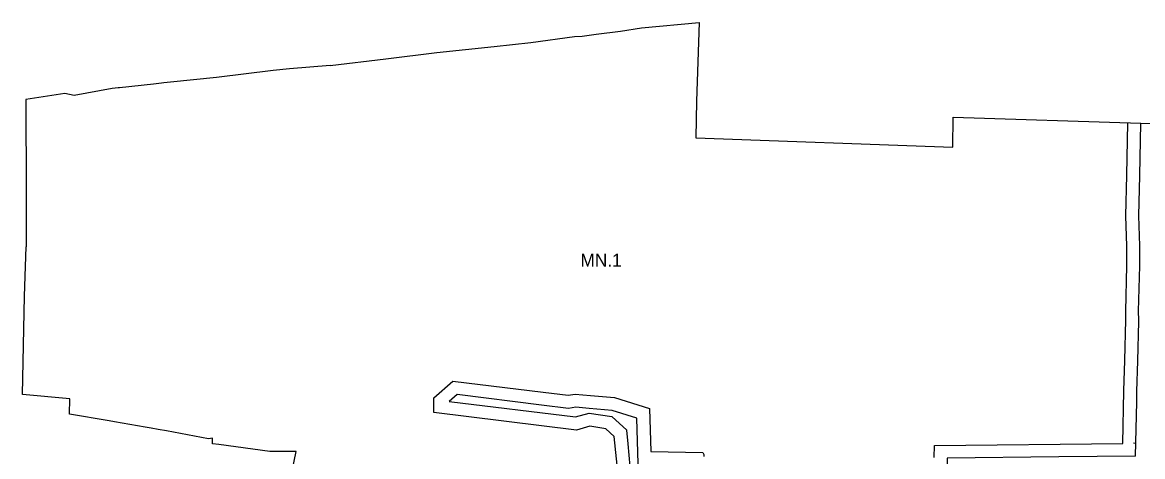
# Model space of a CAD drawing. Extents: x 7414808 to 7417449, y 5544732 to 5546764.
# Drawn here: x 7415345.7 to 7415779, y 5546060.4 to 5546228.6 of the extents above; entities that cross this region are included whole.
import ezdxf

# ---------------------------------------------------------------- set-up
doc = ezdxf.new("R2010")
doc.units = 0
for name, color, linetype in [('LIN_Linie Rozgraniczajace', 7, 'Continuous'), ('LIN_nieprzekraczale linie zabudowy', 7, 'Continuous'), ('TXT_Oznaczenia Przeznaczenia', 7, 'Continuous')]:
    doc.layers.add(name, color=color, linetype=linetype)

msp = doc.modelspace()

# ---------------------------------------------------------------- linework, layer by layer
at = {"layer": 'LIN_Linie Rozgraniczajace'}
for p, q in [((7415464.68, 5546211.88), (7415486.23, 5546214.51)), ((7415778.34, 5546189.58), (7415792.34, 5546189.15)), ((7415346.87, 5546134.03), (7415347.09, 5546141.63)), ((7415579.98, 5546065.34), (7415579.48, 5546070.64))]:
    msp.add_line(p, q, dxfattribs=at)
for points in [[(7415486.23, 5546214.51), (7415506.07, 5546216.92), (7415528.22, 5546219.22), (7415542.33, 5546220.82), (7415559.21, 5546223.15), (7415562.29, 5546223.21), (7415567.6, 5546224.08), (7415577.04, 5546225.19), (7415585.24, 5546226.49), (7415607.49, 5546228.6), (7415606.48, 5546198.05), (7415606.25, 5546183.93), (7415705.62, 5546180.27), (7415705.76, 5546191.84), (7415778.34, 5546189.58)], [(7415464.68, 5546211.88), (7415448.97, 5546210.67), (7415442.64, 5546209.99), (7415420.71, 5546207.28), (7415403.02, 5546205.41), (7415400.36, 5546205.14), (7415399.52, 5546205.05), (7415396.35, 5546204.7), (7415383.24, 5546203.24), (7415382.76, 5546203.19), (7415380.41, 5546202.93), (7415365.7, 5546200.33), (7415362.11, 5546201.04), (7415347.01, 5546198.79), (7415347.12, 5546162.5), (7415347.1, 5546147.03), (7415347.09, 5546141.63)], [(7415776.33, 5546060.55), (7415776.8, 5546081.64), (7415776.85, 5546085.7), (7415777.16, 5546097.57), (7415777.61, 5546112.72), (7415777.59, 5546113.23), (7415777.52, 5546116.75), (7415777.96, 5546134.25), (7415777.92, 5546142.06), (7415777.54, 5546153.67), (7415777.99, 5546169.34), (7415778.34, 5546189.58)], [(7415451.61, 5546062.42), (7415447.67, 5546062.39), (7415441.37, 5546062.35), (7415421.66, 5546065.13), (7415419.21, 5546065.37), (7415419.2, 5546067.57), (7415417.63, 5546067.34), (7415401.38, 5546070.4), (7415398.26, 5546070.93), (7415395.45, 5546071.43), (7415393.11, 5546071.83), (7415381.32, 5546073.87), (7415379.26, 5546074.23), (7415363.91, 5546076.89), (7415364.01, 5546082.81), (7415345.68, 5546084.46), (7415346.53, 5546122.61), (7415346.87, 5546134.03)], [(7415583.85, 5546057.58), (7415583.43, 5546075.3), (7415573.8, 5546078.32), (7415564.97, 5546079.11), (7415559.81, 5546079.62), (7415556.94, 5546079.1), (7415546.52, 5546080.39), (7415513.83, 5546084.43), (7415510.82, 5546081.8), (7415559.62, 5546075.78), (7415564.88, 5546077.31), (7415573.69, 5546075.93), (7415579.48, 5546070.64)], [(7415581.19, 5546053.19), (7415580.8, 5546056.61), (7415579.98, 5546065.34)], [(7415414.67, 5545993.75), (7415420.78, 5546010.4), (7415424.18, 5546016.76), (7415434.02, 5546027.02), (7415447.45, 5546042.45), (7415451.61, 5546062.42)], [(7415776.33, 5546060.55), (7415746.7, 5546060.31), (7415703.42, 5546059.82), (7415703.26, 5546052.85)]]:
    msp.add_lwpolyline(points, dxfattribs=at)
at = {"layer": 'LIN_nieprzekraczale linie zabudowy'}
for points in [[(7415698.42, 5546060.08), (7415698.53, 5546064.76), (7415771.43, 5546065.51), (7415771.85, 5546085.84), (7415772.18, 5546097.62), (7415772.51, 5546113.34), (7415772.55, 5546115.18), (7415772.52, 5546116.76), (7415772.96, 5546134.3), (7415772.92, 5546141.96), (7415772.54, 5546153.66), (7415772.99, 5546169.45), (7415773.34, 5546189.67)], [(7415576.63, 5546048.51), (7415574.66, 5546068.27), (7415571.45, 5546071.2), (7415565.21, 5546072.2), (7415560, 5546070.68), (7415504.83, 5546077.5), (7415504.86, 5546083.24), (7415512.22, 5546089.67), (7415547.13, 5546085.35), (7415556.8, 5546084.16), (7415559.58, 5546084.66), (7415565.44, 5546084.09), (7415574.78, 5546083.25), (7415588.34, 5546079), (7415588.74, 5546062.38), (7415608.9, 5546061.95), (7415609.26, 5546061.21), (7415609.25, 5546060.41)], [(7415776.44, 5546065.55), (7415775.57, 5546065.57)]]:
    msp.add_lwpolyline(points, dxfattribs=at)

# ---------------------------------------------------------------- texts
at = {"layer": 'TXT_Oznaczenia Przeznaczenia'}
msp.add_text('MN.1', height=5, dxfattribs=at).set_placement((7415561.56, 5546134.02))

doc.saveas('drawing.dxf')
